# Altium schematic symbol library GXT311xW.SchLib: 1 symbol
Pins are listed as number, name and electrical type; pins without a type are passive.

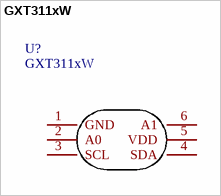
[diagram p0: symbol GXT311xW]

## GXT311xW
designator U?
footprint WLCSP-6-0.695*0.905mm-P0.3mm
pins: 1 GND, 2 A0, 3 SCL, 4 SDA, 5 VDD, 6 A1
